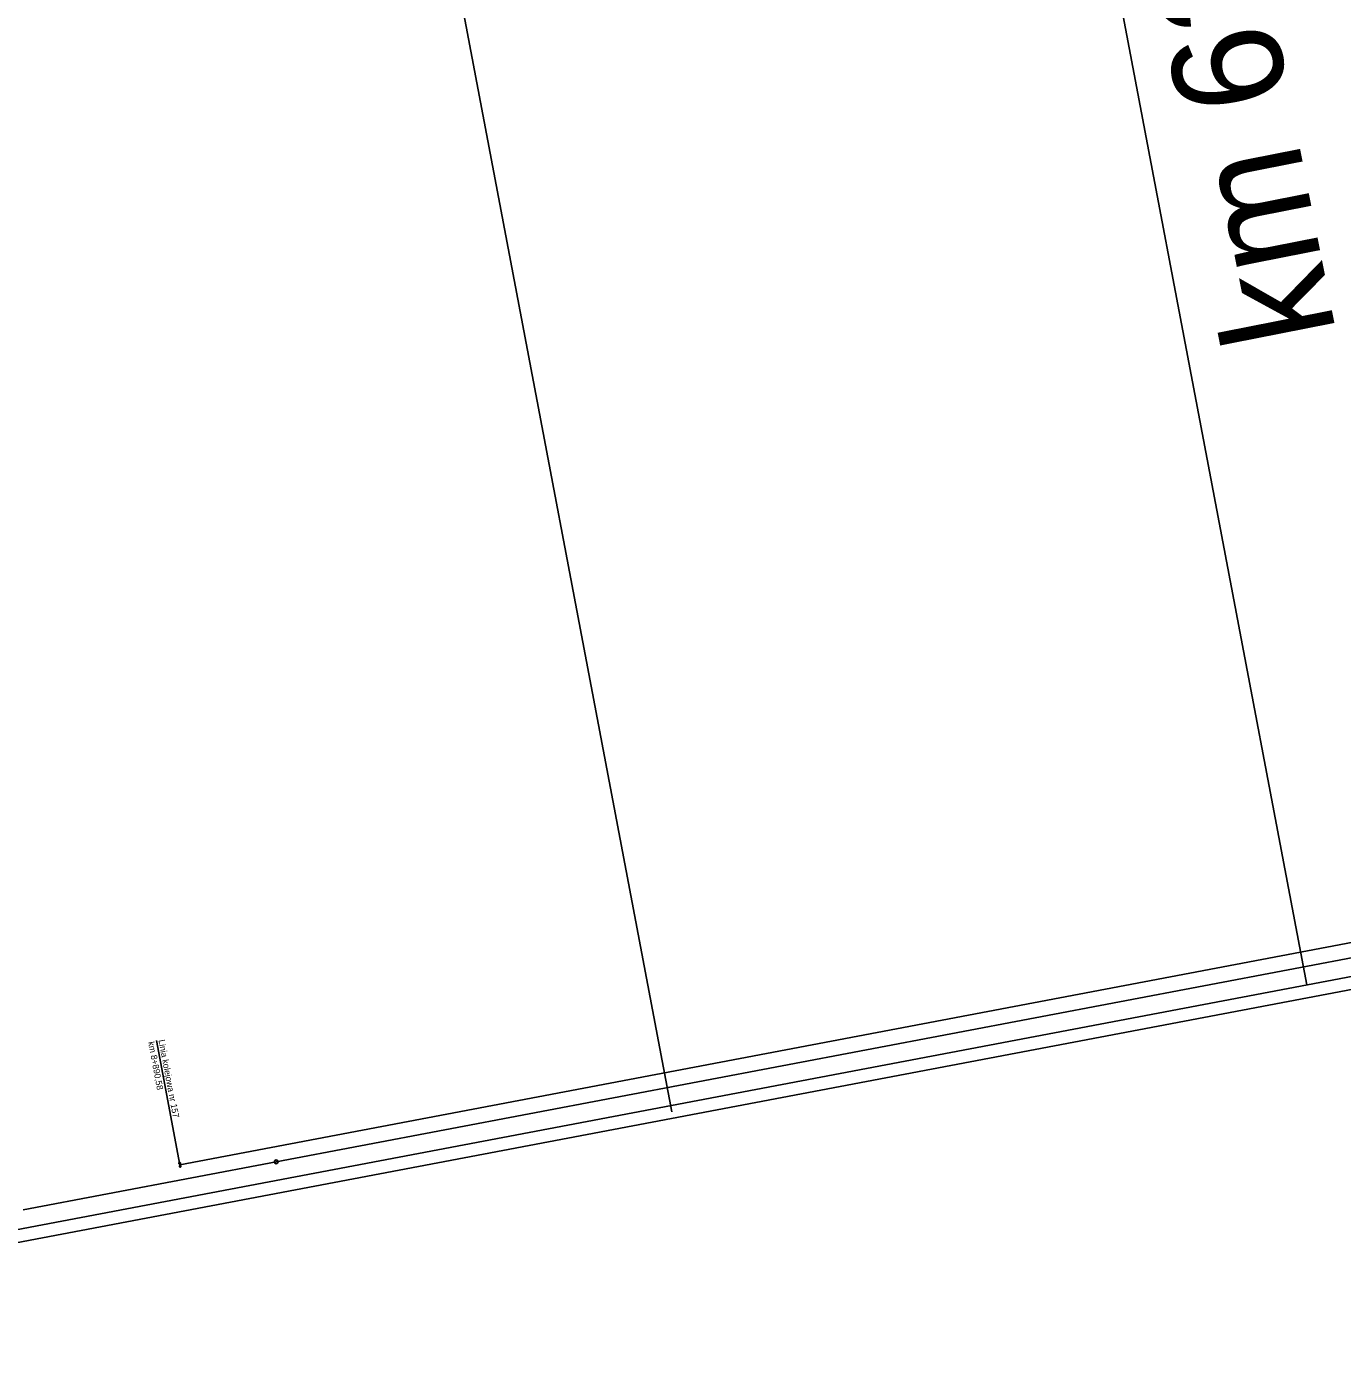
# Model space of a CAD drawing. Extents: x 6540402 to 6566579, y 5525343 to 5532423.
# Drawn here: x 6555919 to 6556335.3, y 5528342.7 to 5528768.7 of the extents above; entities that cross this region are included whole.
import ezdxf

# ---------------------------------------------------------------- set-up
doc = ezdxf.new("R2010")
doc.units = 0
for name, color, linetype in [('IR_ps_geometria', 7, 'Continuous'), ('TOR_PROF-rozjazdy', 7, 'Continuous'), ('TOR_PS_OPIS_T-hektometry projektowane', 7, 'Continuous'), ('TOR_PS_OPIS_T-opisy dodatkowe', 7, 'Continuous'), ('TOR_PS_T-tory projektowane', 7, 'Continuous'), ('TOR_RAMKI-ramka+tabelka 2', 7, 'Continuous')]:
    doc.layers.add(name, color=color, linetype=linetype)

msp = doc.modelspace()

# ---------------------------------------------------------------- linework, layer by layer
at = {"layer": 'IR_ps_geometria'}
msp.add_lwpolyline([(6555967.41, 5528408.66), (6555967.46, 5528408.41), (6555967.49, 5528408.41), (6555967.53, 5528408.41), (6555967.56, 5528408.41), (6555967.59, 5528408.4), (6555967.62, 5528408.39), (6555967.65, 5528408.37), (6555967.67, 5528408.35), (6555967.7, 5528408.33), (6555967.72, 5528408.3), (6555967.73, 5528408.27), (6555967.74, 5528408.24), (6555967.75, 5528408.21), (6555967.76, 5528408.18), (6555967.76, 5528408.15), (6555967.75, 5528408.11), (6555967.74, 5528408.08), (6555967.73, 5528408.05), (6555967.71, 5528408.02), (6555967.69, 5528408), (6555967.67, 5528407.97), (6555967.64, 5528407.95), (6555967.62, 5528407.94), (6555967.58, 5528407.93), (6555967.55, 5528407.92), (6555967.52, 5528407.91), (6555967.49, 5528407.91), (6555967.46, 5528407.92), (6555967.42, 5528407.93), (6555967.39, 5528407.94), (6555967.37, 5528407.96), (6555967.34, 5528407.98), (6555967.32, 5528408), (6555967.3, 5528408.03), (6555967.28, 5528408.06), (6555967.27, 5528408.09), (6555967.26, 5528408.12), (6555967.26, 5528408.15), (6555967.26, 5528408.18), (6555967.26, 5528408.21), (6555967.27, 5528408.25), (6555967.28, 5528408.28), (6555967.3, 5528408.3), (6555967.32, 5528408.33), (6555967.34, 5528408.35), (6555967.37, 5528408.37), (6555967.4, 5528408.39), (6555967.43, 5528408.4), (6555967.46, 5528408.41), (6555967.37, 5528408.9), (6555967.33, 5528408.9), (6555967.3, 5528408.9), (6555967.27, 5528408.9), (6555967.24, 5528408.91), (6555967.21, 5528408.92), (6555967.18, 5528408.94), (6555967.15, 5528408.96), (6555967.13, 5528408.98), (6555967.11, 5528409.01), (6555967.1, 5528409.04), (6555967.08, 5528409.07), (6555967.07, 5528409.1), (6555967.07, 5528409.13), (6555967.07, 5528409.17), (6555967.08, 5528409.2), (6555967.08, 5528409.23), (6555967.1, 5528409.26), (6555967.11, 5528409.29), (6555967.13, 5528409.31), (6555967.16, 5528409.34), (6555967.18, 5528409.36), (6555967.21, 5528409.37), (6555967.24, 5528409.38), (6555967.27, 5528409.39), (6555967.31, 5528409.4), (6555967.34, 5528409.4), (6555967.37, 5528409.39), (6555967.4, 5528409.38), (6555967.43, 5528409.37), (6555967.46, 5528409.35), (6555967.49, 5528409.33), (6555967.51, 5528409.31), (6555967.53, 5528409.28), (6555967.55, 5528409.26), (6555967.56, 5528409.22), (6555967.57, 5528409.19), (6555967.57, 5528409.16), (6555967.57, 5528409.13), (6555967.57, 5528409.1), (6555967.56, 5528409.06), (6555967.54, 5528409.03), (6555967.53, 5528409.01), (6555967.51, 5528408.98), (6555967.48, 5528408.96), (6555967.46, 5528408.94), (6555967.43, 5528408.92), (6555967.4, 5528408.91), (6555967.37, 5528408.9)], close=True, dxfattribs=at)
msp.add_lwpolyline([(6555967.41, 5528408.66), (6555967.46, 5528408.41), (6555967.49, 5528408.41), (6555967.53, 5528408.41), (6555967.56, 5528408.41), (6555967.59, 5528408.4), (6555967.62, 5528408.39), (6555967.65, 5528408.37), (6555967.67, 5528408.35), (6555967.7, 5528408.33), (6555967.72, 5528408.3), (6555967.73, 5528408.27), (6555967.74, 5528408.24), (6555967.75, 5528408.21), (6555967.76, 5528408.18), (6555967.76, 5528408.15), (6555967.75, 5528408.11), (6555967.74, 5528408.08), (6555967.73, 5528408.05), (6555967.71, 5528408.02), (6555967.69, 5528408), (6555967.67, 5528407.97), (6555967.64, 5528407.95), (6555967.62, 5528407.94), (6555967.58, 5528407.93), (6555967.55, 5528407.92), (6555967.52, 5528407.91), (6555967.49, 5528407.91), (6555967.46, 5528407.92), (6555967.42, 5528407.93), (6555967.39, 5528407.94), (6555967.37, 5528407.96), (6555967.34, 5528407.98), (6555967.32, 5528408), (6555967.3, 5528408.03), (6555967.28, 5528408.06), (6555967.27, 5528408.09), (6555967.26, 5528408.12), (6555967.26, 5528408.15), (6555967.26, 5528408.18), (6555967.26, 5528408.21), (6555967.27, 5528408.25), (6555967.28, 5528408.28), (6555967.3, 5528408.3), (6555967.32, 5528408.33), (6555967.34, 5528408.35), (6555967.37, 5528408.37), (6555967.4, 5528408.39), (6555967.43, 5528408.4), (6555967.46, 5528408.41), (6555967.37, 5528408.9), (6555967.33, 5528408.9), (6555967.3, 5528408.9), (6555967.27, 5528408.9), (6555967.24, 5528408.91), (6555967.21, 5528408.92), (6555967.18, 5528408.94), (6555967.15, 5528408.96), (6555967.13, 5528408.98), (6555967.11, 5528409.01), (6555967.1, 5528409.04), (6555967.08, 5528409.07), (6555967.07, 5528409.1), (6555967.07, 5528409.13), (6555967.07, 5528409.17), (6555967.08, 5528409.2), (6555967.08, 5528409.23), (6555967.1, 5528409.26), (6555967.11, 5528409.29), (6555967.13, 5528409.31), (6555967.16, 5528409.34), (6555967.18, 5528409.36), (6555967.21, 5528409.37), (6555967.24, 5528409.38), (6555967.27, 5528409.39), (6555967.31, 5528409.4), (6555967.34, 5528409.4), (6555967.37, 5528409.39), (6555967.4, 5528409.38), (6555967.43, 5528409.37), (6555967.46, 5528409.35), (6555967.49, 5528409.33), (6555967.51, 5528409.31), (6555967.53, 5528409.28), (6555967.55, 5528409.26), (6555967.56, 5528409.22), (6555967.57, 5528409.19), (6555967.57, 5528409.16), (6555967.57, 5528409.13), (6555967.57, 5528409.1), (6555967.56, 5528409.06), (6555967.54, 5528409.03), (6555967.53, 5528409.01), (6555967.51, 5528408.98), (6555967.48, 5528408.96), (6555967.46, 5528408.94), (6555967.43, 5528408.92), (6555967.4, 5528408.91), (6555967.37, 5528408.9)], close=True, dxfattribs=at)
msp.add_lwpolyline([(6555967.41, 5528408.66), (6555967.46, 5528408.41), (6555967.49, 5528408.41), (6555967.53, 5528408.41), (6555967.56, 5528408.41), (6555967.59, 5528408.4), (6555967.62, 5528408.39), (6555967.65, 5528408.37), (6555967.67, 5528408.35), (6555967.7, 5528408.33), (6555967.72, 5528408.3), (6555967.73, 5528408.27), (6555967.74, 5528408.24), (6555967.75, 5528408.21), (6555967.76, 5528408.18), (6555967.76, 5528408.15), (6555967.75, 5528408.11), (6555967.74, 5528408.08), (6555967.73, 5528408.05), (6555967.71, 5528408.02), (6555967.69, 5528408), (6555967.67, 5528407.97), (6555967.64, 5528407.95), (6555967.62, 5528407.94), (6555967.58, 5528407.93), (6555967.55, 5528407.92), (6555967.52, 5528407.91), (6555967.49, 5528407.91), (6555967.46, 5528407.92), (6555967.42, 5528407.93), (6555967.39, 5528407.94), (6555967.37, 5528407.96), (6555967.34, 5528407.98), (6555967.32, 5528408), (6555967.3, 5528408.03), (6555967.28, 5528408.06), (6555967.27, 5528408.09), (6555967.26, 5528408.12), (6555967.26, 5528408.15), (6555967.26, 5528408.18), (6555967.26, 5528408.21), (6555967.27, 5528408.25), (6555967.28, 5528408.28), (6555967.3, 5528408.3), (6555967.32, 5528408.33), (6555967.34, 5528408.35), (6555967.37, 5528408.37), (6555967.4, 5528408.39), (6555967.43, 5528408.4), (6555967.46, 5528408.41), (6555967.37, 5528408.9), (6555967.33, 5528408.9), (6555967.3, 5528408.9), (6555967.27, 5528408.9), (6555967.24, 5528408.91), (6555967.21, 5528408.92), (6555967.18, 5528408.94), (6555967.15, 5528408.96), (6555967.13, 5528408.98), (6555967.11, 5528409.01), (6555967.1, 5528409.04), (6555967.08, 5528409.07), (6555967.07, 5528409.1), (6555967.07, 5528409.13), (6555967.07, 5528409.17), (6555967.08, 5528409.2), (6555967.08, 5528409.23), (6555967.1, 5528409.26), (6555967.11, 5528409.29), (6555967.13, 5528409.31), (6555967.16, 5528409.34), (6555967.18, 5528409.36), (6555967.21, 5528409.37), (6555967.24, 5528409.38), (6555967.27, 5528409.39), (6555967.31, 5528409.4), (6555967.34, 5528409.4), (6555967.37, 5528409.39), (6555967.4, 5528409.38), (6555967.43, 5528409.37), (6555967.46, 5528409.35), (6555967.49, 5528409.33), (6555967.51, 5528409.31), (6555967.53, 5528409.28), (6555967.55, 5528409.26), (6555967.56, 5528409.22), (6555967.57, 5528409.19), (6555967.57, 5528409.16), (6555967.57, 5528409.13), (6555967.57, 5528409.1), (6555967.56, 5528409.06), (6555967.54, 5528409.03), (6555967.53, 5528409.01), (6555967.51, 5528408.98), (6555967.48, 5528408.96), (6555967.46, 5528408.94), (6555967.43, 5528408.92), (6555967.4, 5528408.91), (6555967.37, 5528408.9)], close=True, dxfattribs=at)
at = {"layer": 'TOR_PROF-rozjazdy'}
msp.add_circle((6555997.92, 5528409.6), 0.6, dxfattribs=at)
at = {"layer": 'TOR_PS_OPIS_T-hektometry projektowane'}
msp.add_lwpolyline([(6556123.16, 5528425.43), (6555980.69, 5529177.05)], dxfattribs=at)
at = {"layer": 'TOR_PS_OPIS_T-opisy dodatkowe'}
msp.add_line((6556324.21, 5528465.55), (6556180.84, 5529221.93), dxfattribs=at)
at = {"layer": 'TOR_PS_T-tory projektowane'}
for p, q in [((6557664.82, 5528730.4), (6555967.41, 5528408.66)), ((6556930.18, 5528586.32), (6555917.77, 5528394.41)), ((6556842.83, 5528563.85), (6554354.28, 5528092.14)), ((6556358, 5528467.83), (6550837.09, 5527421.33))]:
    msp.add_line(p, q, dxfattribs=at)
at = {"layer": 'TOR_RAMKI-ramka+tabelka 2'}
msp.add_line((6555967.41, 5528408.66), (6555959.97, 5528447.95), dxfattribs=at)

# ---------------------------------------------------------------- texts
at = {"layer": 'TOR_PS_OPIS_T-opisy dodatkowe'}
msp.add_text('km 62+795(istn.) = km 62+796(proj.)', height=35, rotation=101.1578, dxfattribs=at).set_placement((6556333.52, 5528671.96))
at = {"layer": 'TOR_RAMKI-ramka+tabelka 2'}
for s, p in [('km 8+890,58', (6555957.34, 5528447.45)), ('Linia kolejowa nr 157', (6555960.62, 5528448.07))]:
    msp.add_text(s, height=2, rotation=280.6802, dxfattribs=at).set_placement(p)

doc.saveas('drawing.dxf')
